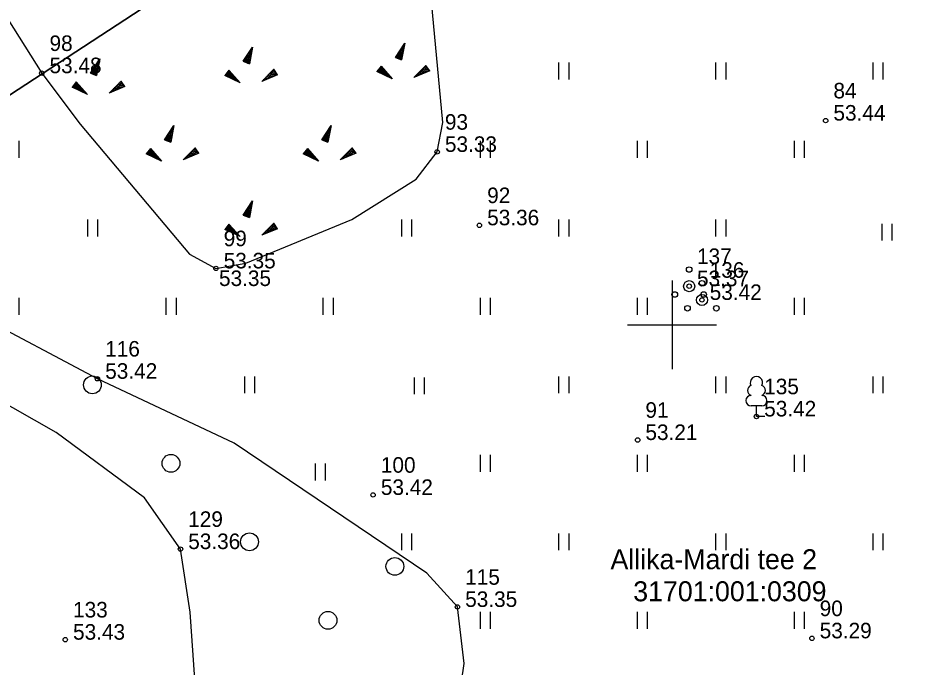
# Model space of a CAD drawing. Extents: x 538599 to 541973, y 6559689 to 6564516.
# Drawn here: x 540570.55 to 540610.89, y 6561284.58 to 6561313.83 of the extents above; entities that cross this region are included whole.
import ezdxf

# ---------------------------------------------------------------- set-up
doc = ezdxf.new("R2010")
doc.units = 0
for name, color, linetype in [('HALJASTUS', 7, 'Continuous'), ('KORGUS-EH2000', 7, 'Continuous'), ('MOOTKORG-EH2000', 7, 'Continuous'), ('MOOTMPUNKT', 7, 'Continuous'), ('MOOTNR', 7, 'Continuous'), ('PIIR', 7, 'Continuous'), ('PUU', 7, 'Continuous'), ('RELJEEF', 7, 'Continuous'), ('VORK', 7, 'Continuous')]:
    doc.layers.add(name, color=color, linetype=linetype)

msp = doc.modelspace()

# ---------------------------------------------------------------- linework, layer by layer
at = {"layer": 'HALJASTUS'}
for p, q in [((540594.89, 6561311.82), (540594.89, 6561311.059)), ((540595.345, 6561311.82), (540595.345, 6561311.059)), ((540601.961, 6561311.82), (540601.961, 6561311.059)), ((540602.416, 6561311.82), (540602.416, 6561311.059)), ((540609.032, 6561311.82), (540609.032, 6561311.059)), ((540609.487, 6561311.82), (540609.487, 6561311.059)), ((540570.596, 6561308.285), (540570.596, 6561307.524)), ((540591.354, 6561308.285), (540591.354, 6561307.524)), ((540591.809, 6561308.285), (540591.809, 6561307.524)), ((540598.425, 6561308.285), (540598.425, 6561307.524)), ((540598.88, 6561308.285), (540598.88, 6561307.524)), ((540605.496, 6561308.285), (540605.496, 6561307.524)), ((540605.951, 6561308.285), (540605.951, 6561307.524)), ((540573.676, 6561304.749), (540573.676, 6561303.988)), ((540574.131, 6561304.749), (540574.131, 6561303.988)), ((540587.818, 6561304.749), (540587.818, 6561303.988)), ((540588.274, 6561304.749), (540588.274, 6561303.988)), ((540594.89, 6561304.749), (540594.89, 6561303.988)), ((540595.345, 6561304.749), (540595.345, 6561303.988)), ((540601.961, 6561304.749), (540601.961, 6561303.988)), ((540602.416, 6561304.749), (540602.416, 6561303.988)), ((540609.439, 6561304.558), (540609.439, 6561303.796)), ((540609.894, 6561304.558), (540609.894, 6561303.796)), ((540570.596, 6561301.214), (540570.596, 6561300.453)), ((540577.212, 6561301.214), (540577.212, 6561300.453)), ((540577.667, 6561301.214), (540577.667, 6561300.453)), ((540584.283, 6561301.214), (540584.283, 6561300.453)), ((540584.738, 6561301.214), (540584.738, 6561300.453)), ((540591.354, 6561301.214), (540591.354, 6561300.453)), ((540591.809, 6561301.214), (540591.809, 6561300.453)), ((540598.425, 6561301.214), (540598.425, 6561300.453)), ((540598.88, 6561301.214), (540598.88, 6561300.453)), ((540605.496, 6561301.214), (540605.496, 6561300.453)), ((540605.951, 6561301.214), (540605.951, 6561300.453)), ((540580.747, 6561297.678), (540580.747, 6561296.917)), ((540581.202, 6561297.678), (540581.202, 6561296.917)), ((540588.387, 6561297.635), (540588.387, 6561296.874)), ((540588.842, 6561297.635), (540588.842, 6561296.874)), ((540594.89, 6561297.678), (540594.89, 6561296.917)), ((540595.345, 6561297.678), (540595.345, 6561296.917)), ((540601.961, 6561297.678), (540601.961, 6561296.917)), ((540602.416, 6561297.678), (540602.416, 6561296.917)), ((540609.032, 6561297.678), (540609.032, 6561296.917)), ((540609.487, 6561297.678), (540609.487, 6561296.917)), ((540591.354, 6561294.143), (540591.354, 6561293.381)), ((540591.809, 6561294.143), (540591.809, 6561293.381)), ((540598.425, 6561294.143), (540598.425, 6561293.381)), ((540598.88, 6561294.143), (540598.88, 6561293.381)), ((540605.496, 6561294.143), (540605.496, 6561293.381)), ((540605.951, 6561294.143), (540605.951, 6561293.381)), ((540583.931, 6561293.756), (540583.931, 6561292.995)), ((540584.386, 6561293.756), (540584.386, 6561292.995)), ((540587.818, 6561290.607), (540587.818, 6561289.846)), ((540588.274, 6561290.607), (540588.274, 6561289.846)), ((540594.89, 6561290.607), (540594.89, 6561289.846)), ((540595.345, 6561290.607), (540595.345, 6561289.846)), ((540601.961, 6561290.607), (540601.961, 6561289.846)), ((540602.416, 6561290.607), (540602.416, 6561289.846)), ((540609.032, 6561290.607), (540609.032, 6561289.846)), ((540609.487, 6561290.607), (540609.487, 6561289.846)), ((540591.354, 6561287.072), (540591.354, 6561286.31)), ((540591.809, 6561287.072), (540591.809, 6561286.31)), ((540598.425, 6561287.072), (540598.425, 6561286.31)), ((540598.88, 6561287.072), (540598.88, 6561286.31)), ((540605.496, 6561287.072), (540605.496, 6561286.31)), ((540605.951, 6561287.072), (540605.951, 6561286.31))]:
    msp.add_line(p, q, dxfattribs=at)
for points in [[(540590.147, 6561281.335), (540590.644, 6561284.753), (540590.335, 6561287.294), (540588.959, 6561288.812), (540580.286, 6561294.676), (540574.128, 6561297.572), (540568.579, 6561300.51), (540565.68, 6561301.441), (540563.181, 6561301.459), (540559.748, 6561300.991), (540557.468, 6561300.029), (540555.748, 6561297.86), (540554.955, 6561296.084), (540554.514, 6561294.385), (540554.129, 6561292.152), (540554.626, 6561287.493), (540554.247, 6561285.697), (540552.955, 6561284.718), (540544.046, 6561282.606)], [(540570.802, 6561276.809), (540573.412, 6561275.976), (540576.87, 6561276.39), (540577.836, 6561277.043), (540578.505, 6561278.71), (540578.609, 6561282.748), (540578.298, 6561287.056), (540577.866, 6561289.9), (540576.248, 6561292.214), (540572.273, 6561295.155), (540567.268, 6561297.994), (540566.387, 6561298.177), (540565.922, 6561297.598), (540564.985, 6561294.225), (540565.068, 6561290.756), (540565.634, 6561288.817), (540567.508, 6561285.194), (540569.933, 6561277.546), (540570.802, 6561276.809)]]:
    msp.add_lwpolyline(points, dxfattribs=at)
for centre in [(540573.904, 6561297.298), (540577.439, 6561293.762), (540580.975, 6561290.226), (540587.519, 6561289.12), (540584.51, 6561286.691)]:
    msp.add_circle(centre, 0.4, dxfattribs=at)
at = {"layer": 'KORGUS-EH2000'}
for centre in [(540571.622, 6561311.338), (540606.914, 6561309.203), (540591.325, 6561304.486), (540579.463, 6561302.544), (540574.128, 6561297.572), (540598.449, 6561294.814), (540586.539, 6561292.34), (540572.681, 6561285.819), (540606.295, 6561285.88)]:
    msp.add_circle(centre, 0.1, dxfattribs=at)
at = {"layer": 'MOOTMPUNKT'}
for centre in [(540571.622, 6561311.338), (540606.914, 6561309.203), (540589.422, 6561307.792), (540591.325, 6561304.486), (540579.463, 6561302.544), (540600.771, 6561301.742), (540601.344, 6561301.124), (540574.128, 6561297.572), (540603.796, 6561295.875), (540598.449, 6561294.814), (540586.539, 6561292.34), (540577.866, 6561289.9), (540590.335, 6561287.294), (540572.681, 6561285.819), (540606.295, 6561285.88)]:
    msp.add_circle(centre, 0.1, dxfattribs=at)
at = {"layer": 'PIIR'}
for points in [[(540501.31, 6561330.86), (540569.6, 6561385.93), (540606.26, 6561333.96), (540535.92, 6561287.97)], [(540535.92, 6561287.97), (540606.26, 6561333.96), (540640.63, 6561283.66), (540573.77, 6561238.75)]]:
    msp.add_lwpolyline(points, close=True, dxfattribs=at)
at = {"layer": 'PUU'}
for p, q in [((540604.036, 6561296.35), (540603.556, 6561296.35)), ((540603.796, 6561295.875), (540603.796, 6561296.35)), ((540604.176, 6561295.875), (540603.796, 6561295.875))]:
    msp.add_line(p, q, dxfattribs=at)
for centre, radius in [((540600.771, 6561302.492), 0.125), ((540600.771, 6561301.742), 0.25), ((540601.344, 6561301.874), 0.125), ((540600.121, 6561301.367), 0.125), ((540601.344, 6561301.124), 0.25), ((540601.421, 6561301.367), 0.125), ((540600.694, 6561300.749), 0.125), ((540601.994, 6561300.749), 0.125)]:
    msp.add_circle(centre, radius, dxfattribs=at)
for centre, radius, start, end in [((540603.796, 6561297.395), 0.277, 332.5799, 207.4201), ((540603.626, 6561297.048), 0.233, 109.0217, 253.1415), ((540603.966, 6561297.048), 0.233, 286.8508, 70.9859), ((540603.559, 6561296.587), 0.238, 90.0016, 269.3953), ((540604.033, 6561296.587), 0.238, 270.6047, 89.9984)]:
    msp.add_arc(centre, radius, start, end, dxfattribs=at)
at = {"layer": 'RELJEEF'}
for p, q in [((540587.541, 6561312.049), (540587.961, 6561312.689)), ((540587.961, 6561312.689), (540587.821, 6561311.934)), ((540587.936, 6561312.649), (540587.956, 6561312.659)), ((540580.689, 6561311.875), (540581.109, 6561312.515)), ((540580.889, 6561312.175), (540581.059, 6561312.25)), ((540580.939, 6561312.25), (540581.069, 6561312.31)), ((540581.109, 6561312.515), (540580.969, 6561311.76)), ((540580.984, 6561312.325), (540581.084, 6561312.365)), ((540581.034, 6561312.4), (540581.094, 6561312.425)), ((540581.084, 6561312.475), (540581.104, 6561312.485)), ((540587.591, 6561312.124), (540587.876, 6561312.244)), ((540587.641, 6561312.199), (540587.891, 6561312.304)), ((540587.691, 6561312.274), (540587.816, 6561312.329)), ((540587.741, 6561312.349), (540587.911, 6561312.424)), ((540587.791, 6561312.424), (540587.921, 6561312.484)), ((540587.816, 6561312.329), (540587.901, 6561312.364)), ((540587.836, 6561312.499), (540587.936, 6561312.539)), ((540587.886, 6561312.574), (540587.946, 6561312.599)), ((540573.814, 6561311.345), (540574.234, 6561311.985)), ((540574.234, 6561311.985), (540574.094, 6561311.23)), ((540574.109, 6561311.795), (540574.209, 6561311.835)), ((540574.159, 6561311.87), (540574.219, 6561311.895)), ((540574.209, 6561311.945), (540574.229, 6561311.955)), ((540580.689, 6561311.875), (540581.014, 6561312.015)), ((540580.689, 6561311.875), (540580.969, 6561311.76)), ((540580.739, 6561311.95), (540581.024, 6561312.07)), ((540580.754, 6561311.85), (540581.004, 6561311.955)), ((540580.789, 6561312.025), (540581.039, 6561312.13)), ((540580.819, 6561311.82), (540580.994, 6561311.895)), ((540580.839, 6561312.1), (540580.964, 6561312.155)), ((540580.889, 6561311.795), (540580.984, 6561311.835)), ((540580.964, 6561312.155), (540581.049, 6561312.19)), ((540587.541, 6561312.049), (540587.866, 6561312.189)), ((540587.541, 6561312.049), (540587.821, 6561311.934)), ((540587.606, 6561312.024), (540587.856, 6561312.129)), ((540587.671, 6561311.994), (540587.846, 6561312.069)), ((540587.741, 6561311.969), (540587.836, 6561312.009)), ((540587.806, 6561311.944), (540587.821, 6561311.949)), ((540573.814, 6561311.345), (540574.139, 6561311.485)), ((540573.864, 6561311.42), (540574.149, 6561311.54)), ((540573.879, 6561311.32), (540574.129, 6561311.425)), ((540573.914, 6561311.495), (540574.164, 6561311.6)), ((540573.964, 6561311.57), (540574.089, 6561311.625)), ((540574.014, 6561311.645), (540574.184, 6561311.72)), ((540574.064, 6561311.72), (540574.194, 6561311.78)), ((540574.089, 6561311.625), (540574.174, 6561311.66)), ((540580.047, 6561311.474), (540579.862, 6561311.234)), ((540580.002, 6561311.419), (540580.037, 6561311.149)), ((540580.047, 6561311.474), (540580.552, 6561310.904)), ((540580.047, 6561311.474), (540580.092, 6561311.124)), ((540580.107, 6561311.409), (540580.147, 6561311.099)), ((540580.954, 6561311.77), (540580.969, 6561311.775)), ((540581.527, 6561310.969), (540582.067, 6561311.514)), ((540582.157, 6561311.379), (540581.972, 6561311.414)), ((540582.117, 6561311.439), (540582.017, 6561311.459)), ((540582.077, 6561311.499), (540582.057, 6561311.499)), ((540582.237, 6561311.264), (540582.067, 6561311.514)), ((540586.899, 6561311.648), (540586.714, 6561311.408)), ((540587.404, 6561311.078), (540586.714, 6561311.408)), ((540586.724, 6561311.423), (540586.729, 6561311.403)), ((540586.769, 6561311.478), (540586.784, 6561311.378)), ((540586.814, 6561311.538), (540586.839, 6561311.353)), ((540586.854, 6561311.593), (540586.889, 6561311.323)), ((540586.899, 6561311.648), (540587.404, 6561311.078)), ((540586.899, 6561311.648), (540586.944, 6561311.298)), ((540586.959, 6561311.583), (540586.999, 6561311.273)), ((540587.019, 6561311.513), (540587.054, 6561311.248)), ((540587.079, 6561311.448), (540587.094, 6561311.308)), ((540588.379, 6561311.143), (540588.919, 6561311.688)), ((540589.089, 6561311.438), (540588.379, 6561311.143)), ((540588.919, 6561311.368), (540588.654, 6561311.418)), ((540589.004, 6561311.403), (540588.699, 6561311.463)), ((540589.089, 6561311.438), (540588.739, 6561311.503)), ((540589.049, 6561311.493), (540588.784, 6561311.548)), ((540589.009, 6561311.553), (540588.824, 6561311.588)), ((540588.969, 6561311.613), (540588.869, 6561311.633)), ((540588.929, 6561311.673), (540588.909, 6561311.673)), ((540589.089, 6561311.438), (540588.919, 6561311.688)), ((540573.814, 6561311.345), (540574.094, 6561311.23)), ((540573.944, 6561311.29), (540574.119, 6561311.365)), ((540574.014, 6561311.265), (540574.109, 6561311.305)), ((540574.079, 6561311.24), (540574.094, 6561311.245)), ((540580.552, 6561310.904), (540579.862, 6561311.234)), ((540579.872, 6561311.249), (540579.877, 6561311.229)), ((540579.917, 6561311.304), (540579.932, 6561311.204)), ((540579.962, 6561311.364), (540579.987, 6561311.179)), ((540580.167, 6561311.339), (540580.202, 6561311.074)), ((540580.227, 6561311.274), (540580.242, 6561311.134)), ((540580.242, 6561311.134), (540580.257, 6561311.044)), ((540580.282, 6561311.204), (540580.312, 6561311.019)), ((540580.342, 6561311.139), (540580.362, 6561310.994)), ((540580.402, 6561311.069), (540580.417, 6561310.969)), ((540580.462, 6561311.004), (540580.472, 6561310.939)), ((540582.237, 6561311.264), (540581.527, 6561310.969)), ((540581.652, 6561311.019), (540581.592, 6561311.034)), ((540581.737, 6561311.054), (540581.632, 6561311.074)), ((540581.817, 6561311.089), (540581.677, 6561311.119)), ((540581.902, 6561311.124), (540581.717, 6561311.159)), ((540581.852, 6561311.184), (540581.762, 6561311.204)), ((540582.067, 6561311.194), (540581.802, 6561311.244)), ((540582.152, 6561311.229), (540581.847, 6561311.289)), ((540581.987, 6561311.159), (540581.852, 6561311.184)), ((540582.237, 6561311.264), (540581.887, 6561311.329)), ((540582.197, 6561311.319), (540581.932, 6561311.374)), ((540587.094, 6561311.308), (540587.109, 6561311.218)), ((540587.134, 6561311.378), (540587.164, 6561311.193)), ((540587.194, 6561311.313), (540587.214, 6561311.168)), ((540587.254, 6561311.243), (540587.269, 6561311.143)), ((540587.314, 6561311.178), (540587.324, 6561311.113)), ((540587.374, 6561311.108), (540587.379, 6561311.088)), ((540588.419, 6561311.158), (540588.404, 6561311.163)), ((540588.504, 6561311.193), (540588.444, 6561311.208)), ((540588.589, 6561311.228), (540588.484, 6561311.248)), ((540588.669, 6561311.263), (540588.529, 6561311.293)), ((540588.754, 6561311.298), (540588.569, 6561311.333)), ((540588.704, 6561311.358), (540588.614, 6561311.378)), ((540588.839, 6561311.333), (540588.704, 6561311.358)), ((540573.172, 6561310.944), (540572.987, 6561310.704)), ((540573.677, 6561310.374), (540572.987, 6561310.704)), ((540572.997, 6561310.719), (540573.002, 6561310.699)), ((540573.042, 6561310.774), (540573.057, 6561310.674)), ((540573.087, 6561310.834), (540573.112, 6561310.649)), ((540573.127, 6561310.889), (540573.162, 6561310.619)), ((540573.172, 6561310.944), (540573.677, 6561310.374)), ((540573.172, 6561310.944), (540573.217, 6561310.594)), ((540573.232, 6561310.879), (540573.272, 6561310.569)), ((540573.292, 6561310.809), (540573.327, 6561310.544)), ((540573.352, 6561310.744), (540573.367, 6561310.604)), ((540573.367, 6561310.604), (540573.382, 6561310.514)), ((540573.407, 6561310.674), (540573.437, 6561310.489)), ((540573.467, 6561310.609), (540573.487, 6561310.464)), ((540574.652, 6561310.439), (540575.192, 6561310.984)), ((540575.362, 6561310.734), (540574.652, 6561310.439)), ((540575.027, 6561310.594), (540574.842, 6561310.629)), ((540574.977, 6561310.654), (540574.887, 6561310.674)), ((540575.192, 6561310.664), (540574.927, 6561310.714)), ((540575.277, 6561310.699), (540574.972, 6561310.759)), ((540575.112, 6561310.629), (540574.977, 6561310.654)), ((540575.362, 6561310.734), (540575.012, 6561310.799)), ((540575.322, 6561310.789), (540575.057, 6561310.844)), ((540575.282, 6561310.849), (540575.097, 6561310.884)), ((540575.242, 6561310.909), (540575.142, 6561310.929)), ((540575.202, 6561310.969), (540575.182, 6561310.969)), ((540575.362, 6561310.734), (540575.192, 6561310.984)), ((540580.522, 6561310.934), (540580.527, 6561310.914)), ((540581.567, 6561310.984), (540581.552, 6561310.989)), ((540573.527, 6561310.539), (540573.542, 6561310.439)), ((540573.587, 6561310.474), (540573.597, 6561310.409)), ((540573.647, 6561310.404), (540573.652, 6561310.384)), ((540574.692, 6561310.454), (540574.677, 6561310.459)), ((540574.777, 6561310.489), (540574.717, 6561310.504)), ((540574.862, 6561310.524), (540574.757, 6561310.544)), ((540574.942, 6561310.559), (540574.802, 6561310.589)), ((540577.153, 6561308.34), (540577.573, 6561308.98)), ((540577.573, 6561308.98), (540577.433, 6561308.225)), ((540584.224, 6561308.34), (540584.644, 6561308.98)), ((540584.644, 6561308.98), (540584.504, 6561308.225)), ((540577.253, 6561308.49), (540577.503, 6561308.595)), ((540577.303, 6561308.565), (540577.428, 6561308.62)), ((540577.353, 6561308.64), (540577.523, 6561308.715)), ((540577.403, 6561308.715), (540577.533, 6561308.775)), ((540577.428, 6561308.62), (540577.513, 6561308.655)), ((540577.448, 6561308.79), (540577.548, 6561308.83)), ((540577.498, 6561308.865), (540577.558, 6561308.89)), ((540577.548, 6561308.94), (540577.568, 6561308.95)), ((540584.324, 6561308.49), (540584.574, 6561308.595)), ((540584.374, 6561308.565), (540584.499, 6561308.62)), ((540584.424, 6561308.64), (540584.594, 6561308.715)), ((540584.474, 6561308.715), (540584.604, 6561308.775)), ((540584.499, 6561308.62), (540584.584, 6561308.655)), ((540584.519, 6561308.79), (540584.619, 6561308.83)), ((540584.569, 6561308.865), (540584.629, 6561308.89)), ((540584.619, 6561308.94), (540584.639, 6561308.95)), ((540577.153, 6561308.34), (540577.478, 6561308.48)), ((540577.153, 6561308.34), (540577.433, 6561308.225)), ((540577.203, 6561308.415), (540577.488, 6561308.535)), ((540577.218, 6561308.315), (540577.468, 6561308.42)), ((540577.283, 6561308.285), (540577.458, 6561308.36)), ((540577.353, 6561308.26), (540577.448, 6561308.3)), ((540577.418, 6561308.235), (540577.433, 6561308.24)), ((540584.224, 6561308.34), (540584.549, 6561308.48)), ((540584.224, 6561308.34), (540584.504, 6561308.225)), ((540584.274, 6561308.415), (540584.559, 6561308.535)), ((540584.289, 6561308.315), (540584.539, 6561308.42)), ((540584.354, 6561308.285), (540584.529, 6561308.36)), ((540584.424, 6561308.26), (540584.519, 6561308.3)), ((540584.489, 6561308.235), (540584.504, 6561308.24)), ((540576.512, 6561307.939), (540576.327, 6561307.699)), ((540576.382, 6561307.769), (540576.397, 6561307.669)), ((540576.427, 6561307.829), (540576.452, 6561307.644)), ((540576.467, 6561307.884), (540576.502, 6561307.614)), ((540576.512, 6561307.939), (540577.017, 6561307.369)), ((540576.512, 6561307.939), (540576.557, 6561307.589)), ((540576.572, 6561307.874), (540576.612, 6561307.564)), ((540576.632, 6561307.804), (540576.667, 6561307.539)), ((540577.991, 6561307.434), (540578.531, 6561307.979)), ((540578.701, 6561307.729), (540578.351, 6561307.794)), ((540578.661, 6561307.784), (540578.396, 6561307.839)), ((540578.621, 6561307.844), (540578.436, 6561307.879)), ((540578.581, 6561307.904), (540578.481, 6561307.924)), ((540578.541, 6561307.964), (540578.521, 6561307.964)), ((540578.701, 6561307.729), (540578.531, 6561307.979)), ((540583.583, 6561307.939), (540583.398, 6561307.699)), ((540583.453, 6561307.769), (540583.468, 6561307.669)), ((540583.498, 6561307.829), (540583.523, 6561307.644)), ((540583.538, 6561307.884), (540583.573, 6561307.614)), ((540583.583, 6561307.939), (540584.088, 6561307.369)), ((540583.583, 6561307.939), (540583.628, 6561307.589)), ((540583.643, 6561307.874), (540583.683, 6561307.564)), ((540583.703, 6561307.804), (540583.738, 6561307.539)), ((540585.062, 6561307.434), (540585.602, 6561307.979)), ((540585.772, 6561307.729), (540585.422, 6561307.794)), ((540585.732, 6561307.784), (540585.467, 6561307.839)), ((540585.692, 6561307.844), (540585.507, 6561307.879)), ((540585.652, 6561307.904), (540585.552, 6561307.924)), ((540585.612, 6561307.964), (540585.592, 6561307.964)), ((540585.772, 6561307.729), (540585.602, 6561307.979)), ((540577.017, 6561307.369), (540576.327, 6561307.699)), ((540576.337, 6561307.714), (540576.342, 6561307.694)), ((540576.692, 6561307.739), (540576.707, 6561307.599)), ((540576.707, 6561307.599), (540576.722, 6561307.509)), ((540576.747, 6561307.669), (540576.777, 6561307.484)), ((540576.807, 6561307.604), (540576.827, 6561307.459)), ((540576.867, 6561307.534), (540576.882, 6561307.434)), ((540576.927, 6561307.469), (540576.937, 6561307.404)), ((540576.987, 6561307.399), (540576.992, 6561307.379)), ((540578.701, 6561307.729), (540577.991, 6561307.434)), ((540578.031, 6561307.449), (540578.016, 6561307.454)), ((540578.116, 6561307.484), (540578.056, 6561307.499)), ((540578.201, 6561307.519), (540578.096, 6561307.539)), ((540578.281, 6561307.554), (540578.141, 6561307.584)), ((540578.366, 6561307.589), (540578.181, 6561307.624)), ((540578.316, 6561307.649), (540578.226, 6561307.669)), ((540578.531, 6561307.659), (540578.266, 6561307.709)), ((540578.616, 6561307.694), (540578.311, 6561307.754)), ((540578.451, 6561307.624), (540578.316, 6561307.649)), ((540584.088, 6561307.369), (540583.398, 6561307.699)), ((540583.408, 6561307.714), (540583.413, 6561307.694)), ((540583.763, 6561307.739), (540583.778, 6561307.599)), ((540583.778, 6561307.599), (540583.793, 6561307.509)), ((540583.818, 6561307.669), (540583.848, 6561307.484)), ((540583.878, 6561307.604), (540583.898, 6561307.459)), ((540583.938, 6561307.534), (540583.953, 6561307.434)), ((540583.998, 6561307.469), (540584.008, 6561307.404)), ((540584.058, 6561307.399), (540584.063, 6561307.379)), ((540585.772, 6561307.729), (540585.062, 6561307.434)), ((540585.102, 6561307.449), (540585.087, 6561307.454)), ((540585.187, 6561307.484), (540585.127, 6561307.499)), ((540585.272, 6561307.519), (540585.167, 6561307.539)), ((540585.352, 6561307.554), (540585.212, 6561307.584)), ((540585.437, 6561307.589), (540585.252, 6561307.624)), ((540585.387, 6561307.649), (540585.297, 6561307.669)), ((540585.602, 6561307.659), (540585.337, 6561307.709)), ((540585.687, 6561307.694), (540585.382, 6561307.754)), ((540585.522, 6561307.624), (540585.387, 6561307.649)), ((540580.689, 6561304.945), (540581.109, 6561305.585)), ((540580.939, 6561305.32), (540581.069, 6561305.38)), ((540581.109, 6561305.585), (540580.969, 6561304.83)), ((540580.984, 6561305.395), (540581.084, 6561305.435)), ((540581.034, 6561305.47), (540581.094, 6561305.495)), ((540581.084, 6561305.545), (540581.104, 6561305.555)), ((540580.689, 6561304.945), (540581.014, 6561305.085)), ((540580.689, 6561304.945), (540580.969, 6561304.83)), ((540580.739, 6561305.02), (540581.024, 6561305.14)), ((540580.754, 6561304.92), (540581.004, 6561305.025)), ((540580.789, 6561305.095), (540581.039, 6561305.2)), ((540580.819, 6561304.89), (540580.994, 6561304.965)), ((540580.839, 6561305.17), (540580.964, 6561305.225)), ((540580.889, 6561305.245), (540581.059, 6561305.32)), ((540580.964, 6561305.225), (540581.049, 6561305.26)), ((540580.047, 6561304.544), (540579.862, 6561304.304)), ((540580.047, 6561304.544), (540580.552, 6561303.974)), ((540580.047, 6561304.544), (540580.092, 6561304.194)), ((540580.889, 6561304.865), (540580.984, 6561304.905)), ((540580.954, 6561304.84), (540580.969, 6561304.845)), ((540581.527, 6561304.039), (540582.067, 6561304.584)), ((540582.077, 6561304.569), (540582.057, 6561304.569)), ((540582.237, 6561304.334), (540582.067, 6561304.584)), ((540580.552, 6561303.974), (540579.862, 6561304.304)), ((540579.872, 6561304.319), (540579.877, 6561304.299)), ((540579.917, 6561304.374), (540579.932, 6561304.274)), ((540579.962, 6561304.434), (540579.987, 6561304.249)), ((540580.002, 6561304.489), (540580.037, 6561304.219)), ((540580.107, 6561304.479), (540580.147, 6561304.169)), ((540580.167, 6561304.409), (540580.202, 6561304.144)), ((540580.227, 6561304.344), (540580.242, 6561304.204)), ((540580.242, 6561304.204), (540580.257, 6561304.114)), ((540580.282, 6561304.274), (540580.312, 6561304.089)), ((540580.342, 6561304.209), (540580.362, 6561304.064)), ((540580.402, 6561304.139), (540580.417, 6561304.039)), ((540582.237, 6561304.334), (540581.527, 6561304.039)), ((540581.737, 6561304.124), (540581.632, 6561304.144)), ((540581.817, 6561304.159), (540581.677, 6561304.189)), ((540581.902, 6561304.194), (540581.717, 6561304.229)), ((540581.852, 6561304.254), (540581.762, 6561304.274)), ((540582.067, 6561304.264), (540581.802, 6561304.314)), ((540582.152, 6561304.299), (540581.847, 6561304.359)), ((540581.987, 6561304.229), (540581.852, 6561304.254)), ((540582.237, 6561304.334), (540581.887, 6561304.399)), ((540582.197, 6561304.389), (540581.932, 6561304.444)), ((540582.157, 6561304.449), (540581.972, 6561304.484)), ((540582.117, 6561304.509), (540582.017, 6561304.529)), ((540580.462, 6561304.074), (540580.472, 6561304.009)), ((540580.522, 6561304.004), (540580.527, 6561303.984)), ((540581.567, 6561304.054), (540581.552, 6561304.059)), ((540581.652, 6561304.089), (540581.592, 6561304.104))]:
    msp.add_line(p, q, dxfattribs=at)
msp.add_lwpolyline([(540589.422, 6561307.792), (540589.68, 6561309.123), (540589.163, 6561314.56), (540588.123, 6561318.281), (540586.874, 6561320.9), (540584.555, 6561323.82), (540581.615, 6561326.678), (540579.576, 6561326.947), (540575.031, 6561326.471), (540570.87, 6561324.462), (540568.551, 6561322.069), (540567.391, 6561319.222), (540568.551, 6561316.219), (540571.622, 6561311.338), (540573.345, 6561309.041), (540578.266, 6561303.19), (540579.463, 6561302.544), (540580.81, 6561302.787), (540585.578, 6561304.743), (540588.479, 6561306.571), (540589.422, 6561307.792)], dxfattribs=at)
at = {"layer": 'VORK'}
for p, q in [((540600, 6561302), (540600, 6561298)), ((540598, 6561300), (540602, 6561300))]:
    msp.add_line(p, q, dxfattribs=at)

# ---------------------------------------------------------------- texts
at = {"layer": 'KORGUS-EH2000'}
for s, p in [('53.48', (540571.972, 6561311.338)), ('53.44', (540607.264, 6561309.203)), ('53.36', (540591.675, 6561304.486)), ('53.35', (540579.602, 6561301.751)), ('53.42', (540574.478, 6561297.572)), ('53.21', (540598.799, 6561294.814)), ('53.42', (540586.889, 6561292.34)), ('53.43', (540573.031, 6561285.819)), ('53.29', (540606.645, 6561285.88))]:
    msp.add_text(s, height=0.7, dxfattribs=at).set_placement(p)
at = {"layer": 'MOOTKORG-EH2000'}
for s, p in [('53.48', (540571.972, 6561311.338)), ('53.44', (540607.264, 6561309.203)), ('53.33', (540589.772, 6561307.792)), ('53.36', (540591.675, 6561304.486)), ('53.35', (540579.813, 6561302.544)), ('53.37', (540601.121, 6561301.742)), ('53.42', (540601.694, 6561301.124)), ('53.42', (540574.478, 6561297.572)), ('53.42', (540604.146, 6561295.875)), ('53.21', (540598.799, 6561294.814)), ('53.42', (540586.889, 6561292.34)), ('53.36', (540578.216, 6561289.9)), ('53.35', (540590.685, 6561287.294)), ('53.43', (540573.031, 6561285.819)), ('53.29', (540606.645, 6561285.88))]:
    msp.add_text(s, height=0.7, dxfattribs=at).set_placement(p)
at = {"layer": 'MOOTNR'}
for s, p in [('98', (540571.972, 6561312.338)), ('84', (540607.264, 6561310.203)), ('93', (540589.772, 6561308.792)), ('92', (540591.675, 6561305.486)), ('99', (540579.813, 6561303.544)), ('137', (540601.121, 6561302.742)), ('136', (540601.694, 6561302.124)), ('116', (540574.478, 6561298.572)), ('135', (540604.146, 6561296.875)), ('91', (540598.799, 6561295.814)), ('100', (540586.889, 6561293.34)), ('129', (540578.216, 6561290.9)), ('115', (540590.685, 6561288.294)), ('133', (540573.031, 6561286.819)), ('90', (540606.645, 6561286.88))]:
    msp.add_text(s, height=0.7, dxfattribs=at).set_placement(p)
at = {"layer": 'PIIR'}
for s, p in [('Allika-Mardi tee 2', (540597.228, 6561288.993)), ('31701:001:0309', (540598.251, 6561287.549))]:
    msp.add_text(s, height=0.9, rotation=360, dxfattribs=at).set_placement(p)

doc.saveas('drawing.dxf')
